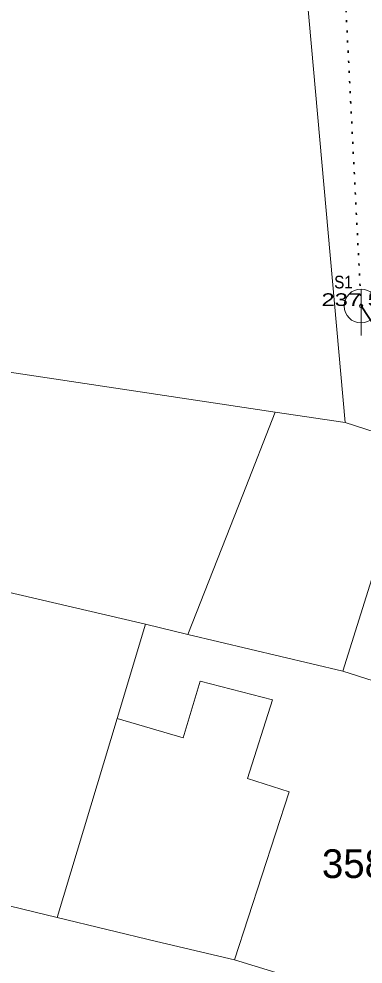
# Model space of a CAD drawing. Extents: x -686207 to -681951, y -1020493 to -1017811.
# Drawn here: x -682512.8 to -682492.4, y -1019020.1 to -1018964.2 of the extents above; entities that cross this region are included whole.
import ezdxf
from ezdxf.enums import TextEntityAlignment as Align

# ---------------------------------------------------------------- set-up
doc = ezdxf.new("R2010")
doc.units = 0
doc.header["$LTSCALE"] = 0.4
doc.header["$PDMODE"] = 32
doc.header["$PDSIZE"] = 0.2
doc.linetypes.add('DOTTED', pattern=[1.5, 0.3, -1.2])
for name, color, linetype, lineweight in [('1', 7, 'Continuous', 13), ('10', 7, 'Continuous', 13), ('3', 7, 'Continuous', 13), ('4', 7, 'Continuous', 13), ('45', 7, 'Continuous', 35), ('46', 7, 'DOTTED', 35)]:
    doc.layers.add(name, color=color, linetype=linetype, lineweight=lineweight)
doc.layers.add('15', color=7, linetype='Continuous')
doc.layers.add('2', color=7, linetype='Continuous')

msp = doc.modelspace()

# ---------------------------------------------------------------- linework, layer by layer
at = {"layer": '1'}
for p, q in [((-682543.91, -1018980.54), (-682497.6, -1018987.44)), ((-682493.45, -1018988.06), (-682497.6, -1018987.44)), ((-682547.25, -1018990.17), (-682505.29, -1018999.99)), ((-682502.77, -1019000.59), (-682505.29, -1018999.99)), ((-682510.51, -1019017.34), (-682518.49, -1019015.41))]:
    msp.add_line(p, q, dxfattribs=at)
for points in [[(-682482.85, -1018956.64), (-682485.61, -1018953.97), (-682490.47, -1018953.26), (-682491.36, -1018960.72), (-682495.96, -1018960.1), (-682493.45, -1018988.06)], [(-682497.6, -1018987.44), (-682499.52, -1018992.34), (-682502.77, -1019000.59)], [(-682493.45, -1018988.06), (-682491.06, -1018988.83), (-682489.34, -1018989.39), (-682480.75, -1018992.16)], [(-682505.29, -1018999.99), (-682506.97, -1019005.56), (-682510.51, -1019017.34)], [(-682502.77, -1019000.59), (-682493.6, -1019002.77), (-682484.99, -1019005.5)], [(-682510.51, -1019017.34), (-682504.64, -1019018.76), (-682500.01, -1019019.84), (-682495.38, -1019021.25), (-682490.47, -1019022.75)]]:
    msp.add_lwpolyline(points, dxfattribs=at)
msp.add_point((-682492.516, -1018981.168), dxfattribs=at)
at = {"layer": '10'}
msp.add_line((-682492.516, -1018980.168), (-682492.516, -1018982.916), dxfattribs=at)
msp.add_circle((-682492.516, -1018981.169), 1.0002, dxfattribs=at)
at = {"layer": '4'}
for p, q in [((-682493.6, -1019002.77), (-682490.44, -1018992.7)), ((-682503.05, -1019006.7), (-682502.04, -1019003.36)), ((-682502.04, -1019003.36), (-682497.77, -1019004.47)), ((-682499.25, -1019009.11), (-682497.77, -1019004.47)), ((-682506.97, -1019005.56), (-682503.05, -1019006.7)), ((-682499.25, -1019009.11), (-682496.78, -1019009.9)), ((-682500.01, -1019019.84), (-682496.78, -1019009.9))]:
    msp.add_line(p, q, dxfattribs=at)
at = {"layer": '45'}
msp.add_line((-682488.285, -1018987.584), (-682492.516, -1018981.168), dxfattribs=at)
at = {"layer": '46'}
msp.add_lwpolyline([(-682492.516, -1018981.168), (-682494.839, -1018935.641), (-682547.461, -1018917.387)], dxfattribs=at)

# ---------------------------------------------------------------- texts
at = {"layer": '15', "width": 0.9}
msp.add_text('S1', height=0.75, rotation=359.98, dxfattribs=at).set_placement((-682493.5586, -1018980.1292), align=Align.CENTER)
at = {"layer": '2'}
msp.add_text('358', height=1.7, dxfattribs=at).set_placement((-682494.834, -1019015))
at = {"layer": '3', "width": 1.4}
msp.add_text('237 57 ', height=0.75, dxfattribs=at).set_placement((-682492.516, -1018981.168), align=Align.CENTER)

doc.saveas('drawing.dxf')
